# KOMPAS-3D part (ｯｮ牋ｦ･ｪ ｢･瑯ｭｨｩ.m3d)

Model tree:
1. Эскиз:1
2. Операция выдавливания:1
     Расстояние 1 = 8
3. Эскиз:2
4. Операция выдавливания:2
     Расстояние 1 = 1
5. Эскиз:3
6. Операция выдавливания:3
     Расстояние 1 = 2.5; Угол 1 = 8
7. Эскиз:4
8. Вырезать элемент выдавливания:1
     Расстояние 1 = 20
9. Эскиз:5
10. Вырезать элемент выдавливания:2
     Расстояние 1 = 3; Угол 1 = 19
11. Скругление:1
     Радиус = 1
12. Скругление:2
     Радиус = 1
13. Скругление:3
     Радиус = 1
14. Эскиз:6
15. Эскиз:7
16. Вырезать элемент выдавливания:3
     Расстояние 1 = 2.5
17. Эскиз:8
18. Вырезать элемент выдавливания:4
     Расстояние 1 = 42
19. Операция выдавливания:4
     Расстояние 1 = 0.8; Расстояние 2 = 1.5
